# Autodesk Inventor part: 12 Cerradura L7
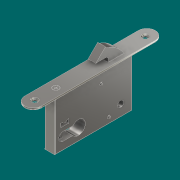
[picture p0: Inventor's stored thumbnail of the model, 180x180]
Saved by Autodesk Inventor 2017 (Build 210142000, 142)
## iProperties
Created: 2019-09
Part Number: 12 Cerradura L7
Material: Acero inoxidable
Document SubType Name: Modeling
Designer: Alfredo Castillo
Density: 8 g/cm^3
Appearance: Semipulido
Mass: 1146.85 g
Surface Area: 306.712 cm^2
Volume: 143.356 cm^3
Comments: Proveedor ITALINNEA Producto CERRADURA DE CORREDERA PARA CILINDRO L7 Marca AGB (ITALIA) Modelo L7 Material ACERO ZINCADO Terminación NIQUELADA, BRONCEADA Y BLACK MATT Instalación Dimensiones Entrada 5
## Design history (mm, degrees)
sketch "Boceto1"
  geometry: L1 (0, 0)-(0, 169); L2 (11, 11)-(11, 158); L3 (-11, 158)-(-11, 11); C1 r 2.75 at (0, 156); C2 r 2.75 at (0, 13); A1 r 11 centre (0, 11) between (-11, 11) and (11, 11); A2 r 11 centre (0, 158) between (11, 158) and (-11, 158); 1 further point
  constraints: 8 end point, 6 point on circle, 4 centre point, 4 point on line, 4 tangent, 1 midpoint, 1 parallel, 1 vertical
  dimensions: "d0" = 169 distance of L1.start L1.end; "d1" = 22 diameter of A2; "d2" = 5.5 diameter of C1; "d3" = 5.5 diameter of C2; "d188" = 13 distance of L1.start C2.centre; "d292" = 13 distance of L1.end C1.centre
extrude "Extrusión1" new body sketch "Boceto1" distance "d6" = 3; taper "d7" = 0 deg
chamfer "Chaflán1" distance "d8" = 1.5; stored, may be unused: second distance "d9" = 2, angle "d10" = 45 deg
fillet "Empalme1" dims "d11" = 1
sketch "Boceto2"
  geometry: L1 (-7, 132.5)-(7, 132.5); L2 (7, 132.5)-(7, 32.5); L3 (7, 32.5)-(-7, 32.5); L4 (-7, 32.5)-(-7, 132.5); L5 (11, 11)-(11, 158) reference; 1 further point
  constraints: 8 end point, 2 parallel, 1 horizontal, 1 perpendicular
  dimensions: "d12" = 100 distance of L1.end L2.end; "d13" = 32.5 distance from line of point (0, 0) L3; "d16" = 14 distance of L1.start L1.end; "d17" = 4 distance between parallel lines of L5 L2
extrude "Extrusión2" join sketch "Boceto2" distance "d14" = 65; taper "d15" = 0 deg
fillet "Empalme7" dims "d50" = 1
sketch "Boceto37"
  geometry: L1 (-49, 3.5)-(-49, 29); L2 (-43.5, 9)-(-43.5, 21.876); L3 (-54.5, 21.876)-(-54.5, 9); L4 (-65, 99)-(-65, -1) reference; L5 (-65, -1)-(0, -1) reference; A1 r 9 centre (-49, 29) between (-43.5, 21.876) and (-54.5, 21.876); A2 r 5.5 centre (-49, 9) between (-54.5, 9) and (-43.5, 9); 4 further points
  constraints: 8 end point, 5 point on circle, 2 centre point, 2 coincident, 2 tangent, 1 midpoint, 1 parallel, 1 point on line, 1 vertical
  dimensions: "d189" = 18 diameter of A1; "d190" = 20 distance of A2.centre A1.centre; "d191" = 10 distance of point (-39.256, 26.751) A1.centre; "d192" = 11 distance between parallel lines of L2 L3; "d293" = 16 distance from line of L4 A1.centre; "d302" = 30 distance from line of L5 A1.centre
extrude "Extrusión32" cut sketch "Boceto37" distance "d193" = 20; taper "d194" = 0 deg
sketch "Boceto42"
  geometry: C1 r 3.75 at (0, 40.407); C2 r 4 at (0, 40.407); 1 further point
  constraints: 2 centre point, 1 coincident
  dimensions: "d213" = 7.5 diameter of C1; "d214" = 8 diameter of C2
extrude "Extrusión37" cut sketch "Boceto42" distance "d215" = 1; taper "d216" = 0 deg
sketch "Boceto43"
  geometry: L1 (-2.006, 0.15)-(-0.661, 0.15); L2 (0.651, 0.15)-(1.994, 0.15); L3 (-2.006, -0.151)-(-0.661, -0.151); L4 (0.65, -0.15)-(1.994, -0.15); L5 (-0.161, -1.995)-(-0.161, -0.651); L6 (-0.161, 0.65)-(-0.161, 2.005); L7 (0.15, -1.996)-(0.15, -0.65); L8 (0.151, 0.65)-(0.151, 2.006); C1 r 3.75 at (0, 0) reference; A1 r 2.011 centre (0, 0) between (0.151, 2.006) and (-0.161, 2.005); A2 r 2.011 centre (0, 0) between (-2.006, 0.15) and (-2.006, -0.151); A3 r 2.002 centre (0, 0) between (-0.161, -1.995) and (0.15, -1.996); A4 r 2 centre (0, 0) between (1.994, -0.15) and (1.994, 0.15); A5 r 0.5 centre (-0.661, 0.65) between (-0.661, 0.15) and (-0.161, 0.65); A6 r 0.5 centre (0.651, 0.65) between (0.151, 0.65) and (0.651, 0.15); A7 r 0.5 centre (-0.661, -0.651) between (-0.161, -0.651) and (-0.661, -0.151); A8 r 0.5 centre (0.65, -0.65) between (0.65, -0.15) and (0.15, -0.65); 5 further points
  constraints: 16 end point, 16 point on circle, 8 centre point, 8 parallel, 8 point on line, 8 tangent, 3 equal radius, 2 horizontal, 2 vertical, 1 coincident
  dimensions: "d231" = 4 distance of L1.start L2.end; "d233" = 4 distance of L5.start L6.end; "d238" = 0.5 radius of A5
extrude "Extrusión38" cut sketch "Boceto43" distance "d236" = 1; taper "d237" = 0 deg
fillet "Empalme27" dims "d251" = 0.5
sketch "Boceto45"
  geometry: L1 (-5, 123)-(5, 123); L2 (5, 123)-(5, 103); L3 (5, 103)-(-5, 103); L4 (-5, 103)-(-5, 123); L5 (-11, 158)-(-11, 11) reference; L6 (5.5, 123.5)-(-5.5, 123.5); L7 (-5.5, 123.5)-(-5.5, 102.5); L8 (-5.5, 102.5)-(5.5, 102.5); L9 (5.5, 102.5)-(5.5, 123.5); A1 r 11 centre (0, 158) between (11, 158) and (-11, 158) reference; 1 further point
  constraints: 16 end point, 4 parallel, 2 perpendicular, 1 horizontal, 3 other
  dimensions: "d273" = 10 distance of L2.end L3.end; "d274" = 20 distance of L1.end L2.end; "d275" = 35 distance from line of L1 A1.centre; "d276" = 6 distance between parallel lines of L5 L4; "d277" = 0.5 distance between parallel lines of L1 L6
extrude "Extrusión40" cut sketch "Boceto45" distance "d278" = 2; taper "d279" = 0 deg
node "Plano de trabajo3"
sketch "Boceto46"
  geometry: L1 (-9.251, 0.004)-(-9.251, 4.504); L2 (-7.251, 6.504)-(6.749, 6.504); L3 (6.749, 6.504)-(-5.751, 19.004); L4 (6.749, 6.504)-(24.427, 6.504); L5 (-5.751, 19.004)-(-6.751, 17.272); L6 (-5.751, 19.004)-(-3.751, 19.004); L7 (-29.248, 0.004)-(-9.251, 0.004); A1 r 39 centre (4.122, -20.182) between (-6.751, 17.272) and (-29.25, 0); A2 r 2 centre (-7.251, 4.504) between (-7.251, 6.504) and (-9.251, 4.504); 3 further points
  constraints: 14 end point, 5 point on circle, 3 horizontal, 2 centre point, 2 equal length, 2 point on line, 2 tangent, 1 perpendicular, 1 vertical
  dimensions: "d282" = 16 distance of point (-9.251, 6.504) L2.end; "d283" = 6.5 distance of L1.start point (-9.251, 6.504); "d284" = 135 deg angle of L4 L3; "d285" = 12.5 horizontal distance of L2.end L3.end; "d286" = 2 distance of L3.end L5.end; "d287" = 120 deg angle of L5 L6; "d288" = 39 radius of A1; "d291" = 2 radius of A2 (derived)
extrude "Extrusión41" join sketch "Boceto46" distance "d289" = 10; taper "d290" = 0 deg
sketch "Boceto48"
  geometry: L1 (-38, 16.468)-(-32.788, 16.468); L2 (-32.788, 16.468)-(-32.788, 14.468); L3 (-38, 6.468)-(-38, 16.468); L4 (-33, 6.468)-(-38, 6.468); L5 (-33, 6.468)-(-33, 8.468); L6 (-65, 99)-(-65, -1) reference; C1 r 4 at (-50, 83.64); C2 r 2.5 at (-57, 68.657); C3 r 2.5 at (-15, 58.668); A1 r 3.183 centre (-31.837, 11.431) between (-32.788, 14.468) and (-33, 8.468); 1 further point
  constraints: 10 end point, 4 centre point, 3 perpendicular, 2 point on circle, 1 horizontal, 1 vertical
  dimensions: "d294" = 5 distance of L4.start L3.start; "d295" = 10 distance of L3.start L1.start; "d296" = 2 distance of L1.end L2.end; "d297" = 2 distance of L4.start L5.end; "d299" = 8 diameter of C1; "d300" = 5 diameter of C2; "d301" = 5 diameter of C3; "d310" = 15 distance from line of L6 C1.centre; "d311" = 8 distance from line of L6 C2.centre; "d312" = 50 distance from line of L6 C3.centre; "d313" = 27 distance between parallel lines of L6 L3
extrude "Extrusión42" cut sketch "Boceto48" distance "d303" = 5; taper "d304" = 0 deg
sketch "Boceto49"
  geometry: C1 r 2 at (0, 0); C2 r 2.5 at (42, -9.989) reference; C3 r 2 at (42, -9.989); 1 further point
  constraints: 2 centre point, 1 coincident
  dimensions: "d305" = 4 diameter of C1; "d306" = 4 diameter of C3
extrude "Extrusión43" join sketch "Boceto49" distance "d307" = 6; taper "d308" = 0 deg
fillet "Empalme34" dims "d309" = 1
sketch "Boceto51"
  geometry: L1 (-36.539, 92.785)-(-35.039, 92.785); L2 (-35.039, 92.785)-(-35.039, 88.785); L3 (-35.039, 88.785)-(-36.539, 88.785); L4 (-36.539, 88.785)-(-36.539, 92.785); 1 further point
  constraints: 8 end point, 2 parallel, 1 horizontal, 1 perpendicular
  dimensions: "d314" = 1.5 distance of L2.end L3.end; "d315" = 4 distance of L1.end L2.end
extrude "Extrusión44" cut sketch "Boceto51" distance "d316" = 1; taper "d317" = 0 deg
fillet "Empalme35" dims "d318" = 2
sketch "Boceto52"
  geometry: L1 (-38, 6.468)-(-38, 16.468) reference; L2 (-33, 6.468)-(-38, 6.468) reference; L3 (-33, 8.468)-(-33, 6.468) reference; L4 (-32.788, 16.468)-(-32.788, 14.468) reference; L5 (-38, 16.468)-(-32.788, 16.468) reference; C1 r 4 at (-50, 83.64) reference; A1 r 3.183 centre (-31.837, 11.431) between (-32.788, 14.468) and (-33, 8.468) reference; 1 further point
extrude "Extrusión45" cut sketch "Boceto52" distance "d319" = 20; taper "d320" = 0 deg
node "Plano de trabajo4"
sketch "Boceto53"
  geometry: C1 r 2.5 at (7, 5); 1 further point
  constraints: 1 centre point
  dimensions: "d322" = 5 diameter of C1
extrude "Extrusión46" join sketch "Boceto53" distance "d323" = 10; taper "d325" = 0 deg; dims "d324" = 20, "d326" = 0
mirror "Simetría2"
fillet "Empalme37" dims "d327" = 1
sketch "Boceto54"
  geometry: 1 further point
node "Sólido1"
node "Contorno proyectado5"
node "Contorno proyectado6"
other parameters: "d94" = 85 deg, "d232" = 0.3, "d234" = 0.3, "d235" = 4, "d280" = 90 deg
